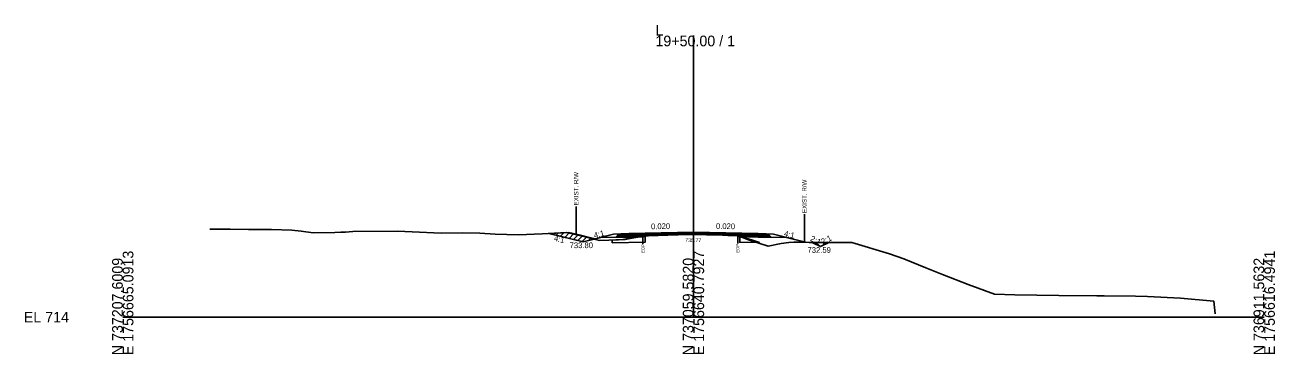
# Model space of a CAD drawing. Extents: x -26 to 4303, y -10 to 9577.
# Drawn here: x -25.7 to 302.8, y 9490.3 to 9576.9 of the extents above; entities that cross this region are included whole.
import ezdxf

# ---------------------------------------------------------------- set-up
doc = ezdxf.new("R2010")
doc.units = 0
for name, color, linetype in [('Exist CMT Pavement', 7, 'Continuous'), ('Old_Level_10', 7, 'Continuous'), ('Old_Level_2', 7, 'Continuous'), ('Pattern 1', 7, 'Continuous'), ('Prop CMT Conc Surface', 7, 'Continuous'), ('Prop CMT Concrete Structures', 7, 'Continuous'), ('Prop CMT Concrete Wall', 7, 'Continuous'), ('Prop CMT Pvmt Course 1', 7, 'Continuous'), ('Prop CMT Pvmt Course 1 CG', 7, 'Continuous'), ('Prop CMT Pvmt Course 1 Wedge', 7, 'Continuous'), ('Prop CMT Pvmt Course 2', 7, 'Continuous'), ('Prop CMT Pvmt Course 2 Wedge', 7, 'Continuous'), ('Prop CMT Pvmt Course 3', 7, 'Continuous'), ('Prop CMT Pvmt Surface', 7, 'Continuous'), ('Prop CMT Pvmt Surface Shoulder', 7, 'Continuous'), ('Prop CMT Pvmt Wedge Surface 1', 7, 'Continuous'), ('Prop CMT Pvmt Wedge Surface 2', 7, 'Continuous'), ('Prop CMT Pvmt Wedge Surface 3', 7, 'Continuous'), ('Prop CMT Shld Paved Course 1', 7, 'Continuous'), ('Prop CMT Shld Paved Course 2', 7, 'Continuous'), ('Prop CMT Shld Paved Course 3', 7, 'Continuous'), ('Prop CMT Slope Grass', 7, 'Continuous'), ('Prop CMT Subgrade Earthwork', 7, 'Continuous'), ('Prop Road Sect_ Recs - UC Shallow (Outline)', 7, 'Continuous'), ('Prop Shade Light', 7, 'Continuous'), ('Prop XS DDE Elevations', 7, 'Continuous'), ('Prop XS Ditch Standard Text', 7, 'Continuous'), ('Prop XS Earthwork Shape', 7, 'Continuous'), ('Prop XS Hydro Elevations', 7, 'Continuous'), ('Prop XS SE Text', 7, 'Continuous'), ('Prop XS Side Slope Text', 7, 'Continuous'), ('Prop XS Wedging', 7, 'Continuous')]:
    doc.layers.add(name, color=color, linetype=linetype)

msp = doc.modelspace()

# ---------------------------------------------------------------- linework, layer by layer
at = {"layer": 'Exist CMT Pavement'}
for points in [[(150, 9522.34), (133, 9522)], [(150, 9522.34), (167, 9522)]]:
    msp.add_lwpolyline(points, dxfattribs=at)
at = {"layer": 'Old_Level_10'}
for p, q in [((181.41, 9519.59), (179.41, 9519.69)), ((183.41, 9518.59), (181.41, 9519.59)), ((185.56, 9519.67), (183.41, 9518.59))]:
    msp.add_line(p, q, dxfattribs=at)
at = {"layer": 'Old_Level_2'}
for p, q in [((150, 9500), (150, 9574.06)), ((150, 9500), (150, 9574.06)), ((0, 9500), (150, 9500)), ((0, 9500), (150, 9500)), ((150, 9500), (300, 9500)), ((150, 9500), (300, 9500))]:
    msp.add_line(p, q, dxfattribs=at)
at = {"layer": 'Pattern 1'}
for p, q in [((112.79, 9521.85), (113.02, 9522.08)), ((113.92, 9521.57), (114.52, 9522.16)), ((115.06, 9521.29), (116.01, 9522.24)), ((116.19, 9521), (117.44, 9522.26)), ((117.32, 9520.72), (118.58, 9521.98)), ((118.45, 9520.44), (119.71, 9521.7)), ((119.58, 9520.15), (120.85, 9521.42)), ((120.71, 9519.87), (121.98, 9521.14)), ((122.41, 9520.15), (123.12, 9520.86))]:
    msp.add_line(p, q, dxfattribs=at)
for points in [[(124.2, 9520.6), (121, 9519.8), (112.1, 9522.03), (117.23, 9522.31), (120.34, 9521.55), (123.03, 9520.89)], [(137.3, 9521.21), (137.3, 9521.35), (136.5, 9521.21)], [(162.18, 9521.22), (162.86, 9521.21), (162.31, 9521.41), (162.18, 9521.43)]]:
    msp.add_lwpolyline(points, close=True, dxfattribs=at)
at = {"layer": 'Prop CMT Conc Surface'}
for points in [[(136.73, 9521.83), (133, 9521.75)], [(133, 9521.75), (133, 9521.55)], [(133, 9521.55), (136.73, 9521.62)], [(136.73, 9521.62), (136.73, 9521.83)], [(161.62, 9521.65), (161.62, 9521.86)], [(161.62, 9521.86), (167, 9521.75)], [(167, 9521.55), (161.62, 9521.65)], [(167, 9521.75), (167, 9521.55)]]:
    msp.add_lwpolyline(points, dxfattribs=at)
at = {"layer": 'Prop CMT Concrete Structures'}
for points in [[(133, 9521.75), (133, 9522)], [(136.73, 9521.83), (133, 9521.75)], [(150, 9522.22), (136.73, 9521.95)], [(136.73, 9521.95), (136.73, 9521.83)], [(150, 9522.22), (161.62, 9521.99)], [(161.62, 9521.99), (161.62, 9521.86)], [(161.62, 9521.86), (167, 9521.75)], [(167, 9521.75), (167, 9522)]]:
    msp.add_lwpolyline(points, dxfattribs=at)
at = {"layer": 'Prop CMT Pvmt Course 1'}
for points in [[(136.73, 9521.62), (133, 9521.55)], [(133, 9521.55), (133, 9521.21)], [(133, 9521.21), (136.73, 9521.29)], [(136.73, 9521.29), (136.73, 9521.62)], [(161.62, 9521.65), (167, 9521.55)], [(161.62, 9521.32), (161.62, 9521.65)], [(167, 9521.21), (161.62, 9521.32)], [(167, 9521.55), (167, 9521.21)]]:
    msp.add_lwpolyline(points, dxfattribs=at)
at = {"layer": 'Prop CMT Pvmt Course 1 Wedge'}
for points in [[(136.73, 9521.62), (136.89, 9521.62), (137.03, 9521.63), (137.48, 9521.63), (137.87, 9521.64), (138.18, 9521.65), (139.45, 9521.67), (140.71, 9521.7), (141.62, 9521.72), (143.24, 9521.75), (145.5, 9521.8), (145.78, 9521.8), (145.97, 9521.8), (147.18, 9521.83), (148.31, 9521.85), (148.32, 9521.85), (149.41, 9521.87), (149.66, 9521.88), (149.98, 9521.88), (150, 9521.89)], [(150, 9521.78), (149.98, 9521.78), (149.66, 9521.78), (149.41, 9521.79), (148.32, 9521.76), (148.31, 9521.76), (147.18, 9521.72), (145.97, 9521.69), (145.78, 9521.68), (145.5, 9521.68), (143.24, 9521.62), (141.62, 9521.55), (140.71, 9521.51), (139.45, 9521.48), (138.18, 9521.45), (137.87, 9521.44), (137.48, 9521.41), (137.03, 9521.4), (136.89, 9521.39), (136.73, 9521.36)], [(136.73, 9521.36), (136.73, 9521.62)], [(150, 9521.89), (150, 9521.78)], [(150, 9521.89), (150.6, 9521.87), (150.84, 9521.87), (151.56, 9521.85), (153.38, 9521.82), (154.59, 9521.79), (155.91, 9521.77), (157.63, 9521.73), (158.44, 9521.72), (159.03, 9521.7), (159.79, 9521.69), (160.89, 9521.67), (161.16, 9521.66), (161.28, 9521.66), (161.44, 9521.66), (161.46, 9521.66), (161.62, 9521.65)], [(161.62, 9521.44), (161.46, 9521.45), (161.44, 9521.45), (161.28, 9521.46), (161.16, 9521.46), (160.89, 9521.47), (159.79, 9521.5), (159.03, 9521.53), (158.44, 9521.54), (157.63, 9521.58), (155.91, 9521.65), (154.59, 9521.66), (153.38, 9521.68), (151.56, 9521.73), (150.84, 9521.75), (150.6, 9521.76), (150, 9521.78)], [(161.62, 9521.65), (161.62, 9521.44)]]:
    msp.add_lwpolyline(points, dxfattribs=at)
at = {"layer": 'Prop CMT Pvmt Course 2'}
for points in [[(133, 9522), (131, 9521.96), (130.74, 9521.71)], [(130.74, 9521.71), (133, 9521.75)], [(133, 9521.75), (133, 9522)], [(167, 9522), (169, 9521.96), (169.26, 9521.71)], [(167, 9521.75), (167, 9522)], [(169.26, 9521.71), (167, 9521.75)]]:
    msp.add_lwpolyline(points, dxfattribs=at)
at = {"layer": 'Prop CMT Pvmt Course 2 Wedge'}
for points in [[(131, 9521.96), (129, 9521.8), (121, 9519.8), (112, 9522.05)], [(169, 9521.96), (171, 9521.8), (179.46, 9519.69)]]:
    msp.add_lwpolyline(points, dxfattribs=at)
at = {"layer": 'Prop CMT Pvmt Course 3'}
for points in [[(133, 9521.75), (130.74, 9521.71), (130.53, 9521.5)], [(130.53, 9521.5), (133, 9521.55)], [(133, 9521.55), (133, 9521.75)], [(167, 9521.75), (169.26, 9521.71), (169.47, 9521.5)], [(167, 9521.55), (167, 9521.75)], [(169.47, 9521.5), (167, 9521.55)]]:
    msp.add_lwpolyline(points, dxfattribs=at)
at = {"layer": 'Prop CMT Pvmt Surface'}
for points in [[(150, 9522.09), (133, 9521.75)], [(133, 9521.75), (133, 9522)], [(150, 9522.09), (167, 9521.75)], [(167, 9521.75), (167, 9522)]]:
    msp.add_lwpolyline(points, dxfattribs=at)
at = {"layer": 'Prop CMT Pvmt Surface Shoulder'}
for points in [[(136.73, 9521.36), (136.89, 9521.39), (137.03, 9521.4), (137.48, 9521.41), (137.87, 9521.44), (138.18, 9521.45), (139.45, 9521.48), (140.71, 9521.51), (141.62, 9521.55), (143.24, 9521.62), (145.5, 9521.68), (145.78, 9521.68), (145.97, 9521.69), (147.18, 9521.72), (148.31, 9521.76), (148.32, 9521.76), (149.41, 9521.79), (149.66, 9521.78), (149.98, 9521.78), (150, 9521.78)], [(150, 9521.78), (150.6, 9521.76), (150.84, 9521.75), (151.56, 9521.73), (153.38, 9521.68), (154.59, 9521.66), (155.91, 9521.65), (157.63, 9521.58), (158.44, 9521.54), (159.03, 9521.53), (159.79, 9521.5), (160.89, 9521.47), (161.16, 9521.46), (161.28, 9521.46), (161.44, 9521.45), (161.46, 9521.45), (161.62, 9521.43)]]:
    msp.add_lwpolyline(points, dxfattribs=at)
at = {"layer": 'Prop CMT Pvmt Wedge Surface 1'}
for p, q in [((133.02, 9521.09), (125.53, 9520.94)), ((136.73, 9521.16), (133.02, 9521.09)), ((161.62, 9521.19), (166.98, 9521.09)), ((166.98, 9521.09), (174.47, 9520.94))]:
    msp.add_line(p, q, dxfattribs=at)
for points in [[(136.73, 9521.16), (136.73, 9521.36)], [(161.62, 9521.19), (161.62, 9521.43)]]:
    msp.add_lwpolyline(points, dxfattribs=at)
at = {"layer": 'Prop CMT Pvmt Wedge Surface 2'}
for points in [[(136.73, 9521.95), (136.89, 9521.96), (137.03, 9521.96), (137.48, 9521.97), (137.87, 9521.98), (138.18, 9521.98), (139.45, 9522.01), (140.71, 9522.03), (141.62, 9522.05), (143.24, 9522.08), (145.5, 9522.13), (145.78, 9522.13), (145.97, 9522.14), (147.18, 9522.16), (148.31, 9522.18), (148.32, 9522.18), (149.41, 9522.21), (149.66, 9522.21), (149.98, 9522.22), (150, 9522.22)], [(150, 9522.09), (149.98, 9522.09), (149.66, 9522.09), (149.41, 9522.08), (148.32, 9522.06), (148.31, 9522.06), (147.18, 9522.04), (145.97, 9522.01), (145.78, 9522.01), (145.5, 9522), (143.24, 9521.96), (141.62, 9521.93), (140.71, 9521.91), (139.45, 9521.88), (138.18, 9521.86), (137.87, 9521.85), (137.48, 9521.84), (137.03, 9521.83), (136.89, 9521.83), (136.73, 9521.83)], [(136.73, 9521.83), (136.73, 9521.95)], [(150, 9522.22), (150, 9522.09)], [(150, 9522.22), (150.6, 9522.21), (150.84, 9522.2), (151.56, 9522.19), (153.38, 9522.15), (154.59, 9522.13), (155.91, 9522.1), (157.63, 9522.07), (158.44, 9522.05), (159.03, 9522.04), (159.79, 9522.02), (160.89, 9522), (161.16, 9522), (161.28, 9521.99), (161.44, 9521.99), (161.46, 9521.99), (161.62, 9521.99)], [(161.62, 9521.86), (161.46, 9521.86), (161.44, 9521.86), (161.28, 9521.87), (161.16, 9521.87), (160.89, 9521.88), (159.79, 9521.9), (159.03, 9521.91), (158.44, 9521.92), (157.63, 9521.94), (155.91, 9521.98), (154.59, 9522), (153.38, 9522.03), (151.56, 9522.06), (150.84, 9522.08), (150.6, 9522.08), (150, 9522.09)], [(161.62, 9521.99), (161.62, 9521.86)]]:
    msp.add_lwpolyline(points, dxfattribs=at)
at = {"layer": 'Prop CMT Pvmt Wedge Surface 3'}
for points in [[(136.73, 9521.83), (136.89, 9521.83), (137.03, 9521.83), (137.48, 9521.84), (137.87, 9521.85), (138.18, 9521.86), (139.45, 9521.88), (140.71, 9521.91), (141.62, 9521.93), (143.24, 9521.96), (145.5, 9522), (145.78, 9522.01), (145.97, 9522.01), (147.18, 9522.04), (148.31, 9522.06), (148.32, 9522.06), (149.41, 9522.08), (149.66, 9522.09), (149.98, 9522.09), (150, 9522.09)], [(150, 9521.89), (149.98, 9521.88), (149.66, 9521.88), (149.41, 9521.87), (148.32, 9521.85), (148.31, 9521.85), (147.18, 9521.83), (145.97, 9521.8), (145.78, 9521.8), (145.5, 9521.8), (143.24, 9521.75), (141.62, 9521.72), (140.71, 9521.7), (139.45, 9521.67), (138.18, 9521.65), (137.87, 9521.64), (137.48, 9521.63), (137.03, 9521.63), (136.89, 9521.62), (136.73, 9521.62)], [(136.73, 9521.62), (136.73, 9521.83)], [(150, 9522.09), (150, 9521.89)], [(150, 9522.09), (150.6, 9522.08), (150.84, 9522.08), (151.56, 9522.06), (153.38, 9522.03), (154.59, 9522), (155.91, 9521.98), (157.63, 9521.94), (158.44, 9521.92), (159.03, 9521.91), (159.79, 9521.9), (160.89, 9521.88), (161.16, 9521.87), (161.28, 9521.87), (161.44, 9521.86), (161.46, 9521.86), (161.62, 9521.86)], [(161.62, 9521.65), (161.46, 9521.66), (161.44, 9521.66), (161.28, 9521.66), (161.16, 9521.66), (160.89, 9521.67), (159.79, 9521.69), (159.03, 9521.7), (158.44, 9521.72), (157.63, 9521.73), (155.91, 9521.77), (154.59, 9521.79), (153.38, 9521.82), (151.56, 9521.85), (150.84, 9521.87), (150.6, 9521.87), (150, 9521.89)], [(161.62, 9521.86), (161.62, 9521.65)]]:
    msp.add_lwpolyline(points, dxfattribs=at)
at = {"layer": 'Prop CMT Shld Paved Course 1'}
for points in [[(133, 9521.55), (133, 9522)], [(150, 9521.89), (133, 9521.55)], [(150, 9521.89), (167, 9521.55)], [(167, 9521.55), (167, 9522)]]:
    msp.add_lwpolyline(points, dxfattribs=at)
at = {"layer": 'Prop CMT Shld Paved Course 2'}
for points in [[(133, 9522), (131, 9521.96)], [(167, 9522), (169, 9521.96)]]:
    msp.add_lwpolyline(points, dxfattribs=at)
at = {"layer": 'Prop CMT Shld Paved Course 3'}
for points in [[(150, 9522.34), (133, 9522)], [(133, 9522), (133, 9521.75)], [(133, 9521.75), (136.73, 9521.83)], [(136.73, 9521.95), (150, 9522.22)], [(136.73, 9521.83), (136.73, 9521.95)], [(150, 9522.34), (167, 9522)], [(161.62, 9521.99), (150, 9522.22)], [(161.62, 9521.86), (161.62, 9521.99)], [(167, 9521.75), (161.62, 9521.86)], [(167, 9522), (167, 9521.75)]]:
    msp.add_lwpolyline(points, dxfattribs=at)
at = {"layer": 'Prop CMT Slope Grass'}
msp.add_lwpolyline([(22.87, 9523.19), (23.48, 9523.16), (24.36, 9523.14), (28.25, 9523.13), (33.03, 9523.08), (39.12, 9523.09), (44.48, 9522.9), (46.93, 9522.66), (50.02, 9522.23), (55.73, 9522.29), (57.28, 9522.32), (58.54, 9522.38), (60.43, 9522.55), (72.17, 9522.63), (76.08, 9522.48), (83.71, 9522.13), (89.19, 9522.21), (93.84, 9522.11), (97.89, 9521.81), (103.98, 9521.7), (110.2, 9521.95), (116.66, 9522.31), (121.57, 9521.11), (125.3, 9520.19), (127.76, 9520.27), (131.44, 9520.42), (136.37, 9521.29), (136.89, 9521.38), (137.48, 9521.4), (137.87, 9521.43), (138.18, 9521.44), (139.44, 9521.47), (140.71, 9521.5), (142.47, 9521.58), (143.24, 9521.61), (145.78, 9521.67), (147.18, 9521.71), (148.32, 9521.75), (149.41, 9521.78), (150, 9521.77), (150.84, 9521.74), (151.56, 9521.72), (153.38, 9521.67), (154.59, 9521.65), (155.91, 9521.64), (157.63, 9521.57), (158.44, 9521.53), (159.03, 9521.52), (159.79, 9521.49), (161.44, 9521.44), (161.75, 9521.41), (164.48, 9520.38), (169.63, 9518.68), (173.02, 9519.34), (175.04, 9519.65), (176.4, 9519.73), (181.32, 9519.66), (191.59, 9519.68), (201.5, 9516.68), (205.33, 9515.37), (211.07, 9512.98), (215.46, 9511.23), (222.21, 9508.58), (229.08, 9506.03), (234.43, 9505.91), (246.04, 9505.66), (256, 9505.59), (257.96, 9505.58), (266.14, 9505.53), (269.3, 9505.43), (278.03, 9505.04), (286.76, 9504.25), (287.15, 9500.84)], dxfattribs=at)
at = {"layer": 'Prop CMT Subgrade Earthwork'}
for points in [[(133, 9521.55), (130.53, 9521.5), (130.03, 9521.49), (129.69, 9521.15)], [(129.69, 9521.15), (133, 9521.21)], [(133, 9521.21), (133, 9521.55)], [(167, 9521.55), (169.47, 9521.5), (169.97, 9521.49), (170.31, 9521.15)], [(167, 9521.21), (167, 9521.55)], [(170.31, 9521.15), (167, 9521.21)]]:
    msp.add_lwpolyline(points, dxfattribs=at)
at = {"layer": 'Prop Road Sect_ Recs - UC Shallow (Outline)'}
for points in [[(128.64, 9519.54), (137.3, 9519.71), (137.3, 9521.21), (136.4, 9521.19), (134.83, 9520.92), (133.36, 9520.66), (132.02, 9520.42), (128.62, 9520.28)], [(167.33, 9519.62), (162.18, 9519.72), (162.18, 9521.22), (162.86, 9521.21), (164.66, 9520.53), (165.23, 9520.32)]]:
    msp.add_lwpolyline(points, close=True, dxfattribs=at)
at = {"layer": 'Prop Shade Light'}
for points in [[(128.64, 9519.54), (137.3, 9519.71), (137.3, 9521.21), (136.4, 9521.19), (134.83, 9520.92), (133.36, 9520.66), (132.02, 9520.42), (128.62, 9520.28), (128.64, 9519.54)], [(128.64, 9519.54), (137.3, 9519.71), (137.3, 9521.21), (136.4, 9521.19), (134.83, 9520.92), (133.36, 9520.66), (132.02, 9520.42), (128.62, 9520.28), (128.64, 9519.54)], [(165.23, 9520.32), (164.66, 9520.53), (162.86, 9521.21), (162.18, 9521.22), (162.18, 9519.72), (167.33, 9519.62), (165.23, 9520.32)]]:
    msp.add_lwpolyline(points, dxfattribs=at)
at = {"layer": 'Prop XS DDE Elevations'}
for points in [[(121.57, 9521.11), (123.91, 9520.53), (121, 9519.8), (112, 9522.05), (116.66, 9522.31)], [(127.76, 9520.27), (131.44, 9520.42), (135.51, 9521.14), (133.02, 9521.09), (125.53, 9520.94), (123.91, 9520.53), (125.3, 9520.19)], [(136.37, 9521.29), (136.73, 9521.36), (136.73, 9521.16), (135.51, 9521.14)], [(136.89, 9521.39), (137.48, 9521.41), (137.03, 9521.4)], [(139.45, 9521.48), (140.71, 9521.51), (139.44, 9521.47), (138.18, 9521.45)], [(140.71, 9521.51), (142.47, 9521.58), (143.24, 9521.62), (141.62, 9521.55)], [(145.5, 9521.68), (145.78, 9521.68), (143.24, 9521.62)], [(145.78, 9521.68), (147.18, 9521.72), (145.97, 9521.69)], [(148.31, 9521.76), (148.32, 9521.76), (147.18, 9521.72)], [(149.41, 9521.79), (149.66, 9521.78), (149.98, 9521.78), (150, 9521.78), (150.6, 9521.76), (150.84, 9521.75), (150, 9521.77)], [(159.79, 9521.5), (161.03, 9521.47), (160.89, 9521.47)], [(161.28, 9521.46), (161.44, 9521.45), (161.03, 9521.47), (161.16, 9521.46)], [(161.44, 9521.45), (161.46, 9521.45), (161.62, 9521.43)], [(161.75, 9521.41), (162.37, 9521.18), (161.62, 9521.19), (161.62, 9521.43)], [(166.98, 9521.09), (174.47, 9520.94), (179.46, 9519.69), (176.4, 9519.73), (175.04, 9519.65), (173.02, 9519.34), (169.63, 9518.68), (164.48, 9520.38), (162.37, 9521.18)]]:
    msp.add_lwpolyline(points, close=True, dxfattribs=at)
at = {"layer": 'Prop XS Ditch Standard Text'}
for p, q in [((119.16, 9529.1), (119.16, 9521.7)), ((179.16, 9527.09), (179.16, 9519.69)), ((136.73, 9521.35), (136.73, 9519.3)), ((161.62, 9521.43), (161.62, 9519.38))]:
    msp.add_line(p, q, dxfattribs=at)
at = {"layer": 'Prop XS Earthwork Shape'}
msp.add_lwpolyline([(185.56, 9519.67), (183.41, 9518.59), (181.41, 9519.59), (179.42, 9519.69), (181.32, 9519.66)], close=True, dxfattribs=at)
at = {"layer": 'Prop XS Wedging'}
for p, q in [((150, 9522.22), (136.73, 9521.95)), ((136.73, 9521.83), (150, 9522.09)), ((136.73, 9521.83), (150, 9522.09)), ((136.73, 9521.95), (136.73, 9521.83)), ((136.73, 9521.83), (136.73, 9521.62)), ((136.73, 9521.62), (136.73, 9521.36)), ((136.73, 9521.36), (136.73, 9521.35)), ((161.62, 9521.99), (150, 9522.22)), ((161.61, 9521.86), (150, 9522.09)), ((150, 9522.09), (150, 9522.09)), ((150, 9522.09), (150, 9522.09)), ((150, 9522.09), (161.62, 9521.86)), ((161.62, 9521.86), (161.62, 9521.99)), ((161.62, 9521.65), (161.62, 9521.86)), ((161.62, 9521.44), (161.62, 9521.65))]:
    msp.add_line(p, q, dxfattribs=at)
for points in [[(150, 9522.09), (150, 9522.09), (136.73, 9521.83)], [(136.73, 9521.35), (136.89, 9521.38), (137.48, 9521.4), (137.87, 9521.43), (138.18, 9521.44), (139.44, 9521.47), (140.71, 9521.5), (142.47, 9521.58), (143.24, 9521.61), (145.78, 9521.67), (147.18, 9521.71), (148.32, 9521.75), (149.41, 9521.78), (150, 9521.77), (150.84, 9521.74), (151.56, 9521.72), (153.38, 9521.67), (154.59, 9521.65), (155.91, 9521.64), (157.63, 9521.57), (158.44, 9521.53), (159.03, 9521.52), (159.79, 9521.49), (161.44, 9521.44), (161.62, 9521.43)], [(136.73, 9521.36), (136.73, 9521.36)], [(150, 9522.09), (150, 9522.09)], [(150, 9522.09), (150, 9522.09)], [(161.62, 9521.86), (150, 9522.09), (150, 9522.09)], [(161.62, 9521.43), (161.62, 9521.43), (161.62, 9521.44)], [(161.62, 9521.44), (161.62, 9521.44)]]:
    msp.add_lwpolyline(points, dxfattribs=at)

# ---------------------------------------------------------------- texts
at = {"layer": 'Old_Level_2'}
for s, p in [('L', (140, 9574.06)), ('L', (140, 9574.06)), ('19+50.00 / 1', (140, 9571.26)), ('19+50.00 / 1', (140, 9571.26)), ('EL 714', (-26, 9498.6)), ('EL 714', (-26, 9498.6))]:
    msp.add_text(s, height=2.8, dxfattribs=at).set_placement(p)
for s, p in [('N 737207.6009', (0, 9490)), ('N 737207.6009', (0, 9490)), ('E 1756665.0913', (2.8, 9490)), ('E 1756665.0913', (2.8, 9490)), ('N 737059.5820', (150, 9490)), ('N 737059.5820', (150, 9490)), ('E 1756640.7927', (152.8, 9490)), ('E 1756640.7927', (152.8, 9490)), ('N 736911.5632', (300, 9490)), ('N 736911.5632', (300, 9490)), ('E 1756616.4941', (302.8, 9490)), ('E 1756616.4941', (302.8, 9490))]:
    msp.add_text(s, height=2.8, rotation=90, dxfattribs=at).set_placement(p)
at = {"layer": 'Prop CMT Concrete Wall'}
for rotation, p in [(334.1383, (180.56, 9520.17)), (25.8617, (183.99, 9519.09))]:
    msp.add_text('2:1', height=1.5, rotation=rotation, dxfattribs=at).set_placement(p)
msp.add_text('732.59', height=1.5, dxfattribs=at).set_placement((179.98, 9516.93))
at = {"layer": 'Prop CMT Pvmt Course 1 CG'}
msp.add_text('735.77', height=1, dxfattribs=at).set_placement((147.85, 9519.77))
at = {"layer": 'Prop XS Ditch Standard Text'}
for s, height, p in [('EXIST. R/W', 1.181, (119.75, 9529.4)), ('EXIST. R/W', 1.181, (179.75, 9527.4)), ('EOP', 0.787, (137.13, 9516.9)), ('EOP', 0.787, (162.01, 9516.98))]:
    msp.add_text(s, height=height, rotation=90, dxfattribs=at).set_placement(p)
at = {"layer": 'Prop XS Hydro Elevations'}
msp.add_text('733.80', height=1.5, dxfattribs=at).set_placement((117.45, 9518.16))
at = {"layer": 'Prop XS SE Text'}
for rotation, p in [(1.1458, (138.86, 9523.12)), (358.8542, (155.9, 9523.23))]:
    msp.add_text('0.020', height=1.5, rotation=rotation, dxfattribs=at).set_placement(p)
at = {"layer": 'Prop XS Side Slope Text'}
for rotation, p in [(345.9638, (113.22, 9520.13)), (14.0362, (124, 9520.77)), (345.9638, (173.67, 9521.36))]:
    msp.add_text('4:1', height=1.5, rotation=rotation, dxfattribs=at).set_placement(p)

doc.saveas('drawing.dxf')
